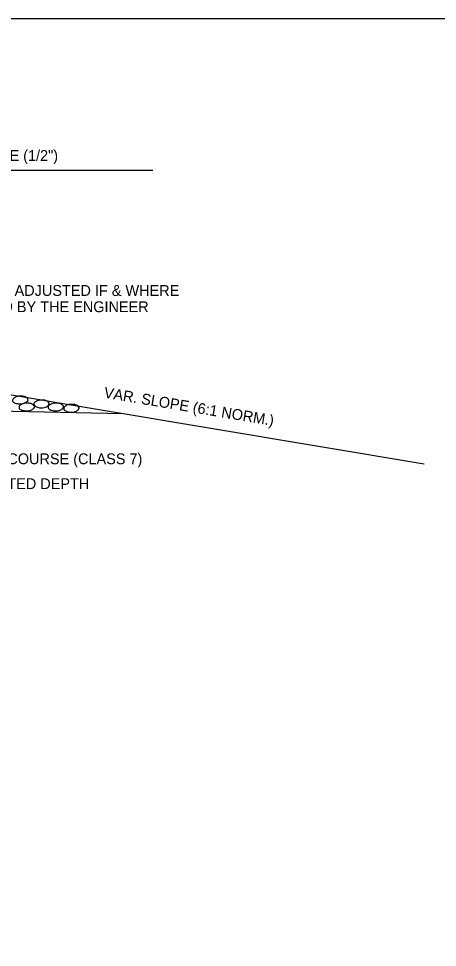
# Model space of a CAD drawing. Extents: x 1929624 to 1935547, y 596315 to 605721.
# Drawn here: x 1933139 to 1933371, y 604033 to 604548 of the extents above; entities that cross this region are included whole.
import ezdxf

# ---------------------------------------------------------------- set-up
doc = ezdxf.new("R2010")
doc.units = 0
doc.layers.add('Default', color=7, linetype='Continuous')
doc.layers.add('R_Annotation', color=7, linetype='Continuous')

msp = doc.modelspace()

# ---------------------------------------------------------------- linework, layer by layer
at = {"layer": 'Default'}
for p, q in [((1933213.06, 604463.38), (1932972.32, 604463.38)), ((1932972.32, 604366.13), (1933363.55, 604300.92)), ((1932793.72, 604336.78), (1933196.64, 604328.73))]:
    msp.add_line(p, q, dxfattribs=at)
for points in [[(1933139.43, 604338.3), (1933140.94, 604338.29), (1933142.77, 604337.65), (1933143.69, 604336.79), (1933143.83, 604336.29), (1933143.33, 604335.36), (1933142.8, 604334.93), (1933141.83, 604334.45), (1933140.32, 604334.08), (1933139.59, 604334.03), (1933138.45, 604334.11), (1933137.24, 604334.33), (1933136.29, 604334.72), (1933135.4, 604335.42), (1933135.26, 604336.04), (1933135.52, 604336.82), (1933136.21, 604337.38), (1933136.86, 604337.82), (1933137.84, 604338.14), (1933138.47, 604338.29), (1933139.43, 604338.3)], [(1933143.03, 604334.45), (1933144.54, 604334.44), (1933146.37, 604333.8), (1933147.29, 604332.94), (1933147.43, 604332.44), (1933146.93, 604331.51), (1933146.4, 604331.09), (1933145.43, 604330.6), (1933143.92, 604330.23), (1933143.19, 604330.18), (1933142.05, 604330.26), (1933140.84, 604330.48), (1933139.89, 604330.87), (1933139, 604331.57), (1933138.86, 604332.19), (1933139.12, 604332.97), (1933139.81, 604333.53), (1933140.46, 604333.97), (1933141.44, 604334.3), (1933142.07, 604334.44), (1933143.03, 604334.45)], [(1933151.21, 604336.13), (1933152.73, 604336.12), (1933154.55, 604335.48), (1933155.47, 604334.62), (1933155.61, 604334.12), (1933155.11, 604333.19), (1933154.58, 604332.77), (1933153.61, 604332.29), (1933152.1, 604331.91), (1933151.37, 604331.86), (1933150.23, 604331.94), (1933149.02, 604332.16), (1933148.07, 604332.55), (1933147.18, 604333.25), (1933147.04, 604333.88), (1933147.3, 604334.65), (1933147.99, 604335.22), (1933148.64, 604335.65), (1933149.62, 604335.98), (1933150.25, 604336.12), (1933151.21, 604336.13)], [(1933159.15, 604334.45), (1933160.66, 604334.44), (1933162.48, 604333.8), (1933163.4, 604332.94), (1933163.54, 604332.44), (1933163.04, 604331.51), (1933162.51, 604331.09), (1933161.55, 604330.6), (1933160.03, 604330.23), (1933159.3, 604330.18), (1933158.16, 604330.26), (1933156.95, 604330.48), (1933156, 604330.87), (1933155.11, 604331.57), (1933154.97, 604332.19), (1933155.23, 604332.97), (1933155.92, 604333.53), (1933156.57, 604333.97), (1933157.56, 604334.3), (1933158.18, 604334.44), (1933159.15, 604334.45)], [(1933167.79, 604333.73), (1933169.31, 604333.72), (1933171.13, 604333.08), (1933172.05, 604332.22), (1933172.19, 604331.72), (1933171.69, 604330.79), (1933171.16, 604330.37), (1933170.19, 604329.89), (1933168.68, 604329.51), (1933167.95, 604329.47), (1933166.81, 604329.54), (1933165.6, 604329.76), (1933164.65, 604330.15), (1933163.76, 604330.85), (1933163.62, 604331.48), (1933163.88, 604332.25), (1933164.57, 604332.82), (1933165.22, 604333.25), (1933166.2, 604333.58), (1933166.83, 604333.72), (1933167.79, 604333.73)]]:
    msp.add_spline(points, degree=3, dxfattribs=at)
at = {"layer": 'R_Annotation'}
msp.add_lwpolyline([(1932708, 604547.56), (1933362.58, 604547.56), (1933392.36, 604547.56), (1933392.36, 604032.86)], dxfattribs=at)

# ---------------------------------------------------------------- texts
at = {"layer": 'Default'}
for s, p in [('VAR. WIDTH ACHM SURFACE COURSE (1/2")', (1932988.71, 604468.7)), ('* THIS WIDTH MAY BE ADJUSTED IF & WHERE ', (1933049.46, 604393.88)), ('DIRECTED BY THE ENGINEER', (1933094.43, 604384.88)), ('AGGREGATE BASE COURSE (CLASS 7)', (1933055.68, 604300.62)), ('VARIABLE COMPACTED DEPTH', (1933055.68, 604286.83))]:
    msp.add_text(s, height=6, dxfattribs=at).set_placement(p)
msp.add_text('VAR. SLOPE (6:1 NORM.)', height=6, rotation=350.5384, dxfattribs=at).set_placement((1933185.63, 604337.52))

doc.saveas('drawing.dxf')
